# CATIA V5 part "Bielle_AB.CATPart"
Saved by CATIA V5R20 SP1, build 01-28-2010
Part number: Bielle AB
Publications: "Diamètre bielle", "Diamètre pivot", "Epaisseur pivot", "Longueur axe pivot", "Point.3", "Plan.3", "Corps principal"
Bounding box of the stored display mesh (mm): x -9 to 12, y -3.975 to 6.117, z -3.975 to 13.773
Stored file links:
  C:\Documents and Settings\pschann\Bureau\IAO\Bielle_AB.CATPart
  C:\Documents and Settings\pschann\Bureau\IAO\pschann.CATProduct
  J:\Projet\CAO\Bielle BC.CATPart
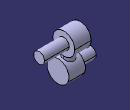
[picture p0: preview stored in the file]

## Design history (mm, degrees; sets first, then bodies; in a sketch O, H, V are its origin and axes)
Parameters
  `Diamètre bielle` = 4 mm
  `Diamètre pivot` = 4 mm
  `Epaisseur pivot` = 2 mm
  `Longueur axe pivot` = 6 mm
Set1
  Plane1: type Normal, Curve Line1, RefPoint Point1
  Sketch1 on Plane1, origin (0, 0, 0), H (1, 0, 0), V (0, 0.9773, -0.2117)
    circle A1 centre (0, 0) radius 2
    radius A1 = 2 {= `Diamètre bielle` /2}
  Plane2: type Normal, Curve Line1, RefPoint Point2
Set2
  Line1: linked copy from another document
  Point1 "A": linked copy from another document
  Point2 "B": linked copy from another document
Body1 (main body)
  Pad1: profile Sketch1, direction (0, 0.2117, 0.9773), up to Plane2
  Sketch2 on yz-plane, origin (0, 0, 0), H (0, 1, 0), V (0, 0, 1)
    circle A1 centre (2.1167, 9.7734) radius 4
    point P1 (2.1167, 9.7734)
    reference projected point E1 (2.1167, 9.7734) from Point2
    radius A1 = 4 {= `Diamètre pivot` /2+`Epaisseur pivot`}
    coincidence: P1 E1
  Pad2: profile Sketch2, direction (1, 0, 0), length 3 {= `Longueur axe pivot` /2}, mirrored extent
  Point3: type Between, FirstPoint Point2, SecondPoint Point1, Ratio 0.5, Support Line1
  Plane3: type Normal, Curve Line1, RefPoint Point3
  Sketch3 on end face of Pad2, origin (3, 0, 0), H (0, 1, 0), V (0, 0, 1)
    circle A1 centre (2.1167, 9.7734) radius 2
    reference projected circle E1 centre (2.1167, 9.7734) radius 4 from edge [face of Pad2 from Sketch2.A1 | end face of Pad2]
    radius A1 = 2 {= `Diamètre pivot` /2}
    concentricity: A1 E1
  Pad3: profile Sketch3, direction (1, 0, 0), length 9 {= `Longueur axe pivot` *1.5}
  Mirror1: of Pad2, about Plane3
  Sketch4 on face of Mirror1, origin (-3, 0, 0), H (0, -1, 0), V (0, 0, 1)
    circle A1 centre (0, 0) radius 2
    reference projected circle E1 centre (0, 0) radius 4 from edge [face of Mirror1 | face of Mirror1]
    radius A1 = 2 {= `Diamètre pivot` /2}
    concentricity: A1 E1
  Pad4: profile Sketch4, direction (-1, 0, 0), length 6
